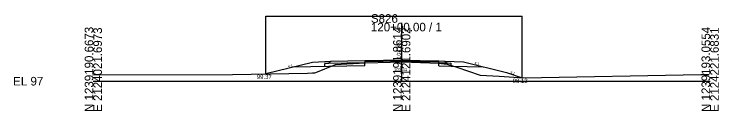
# Model space of a CAD drawing. Extents: x 2119282 to 2119710, y 1215030 to 1220057.
# Drawn here: x 2119381.9 to 2119610.4, y 1218530.1 to 1218561.7 of the extents above; entities that cross this region are included whole.
import ezdxf

# ---------------------------------------------------------------- set-up
doc = ezdxf.new("R2010")
doc.units = 0
for name, color, linetype in [('XS_CELL', 7, 'Continuous'), ('XS_M_DITCH', 7, 'Continuous'), ('XS_P_FINISHED_GRADE', 7, 'Continuous'), ('XS_P_FINISHED_GRADE_ELEV_TX', 7, 'Continuous'), ('XS_P_SUBGRADE_GRANULAR', 7, 'Continuous'), ('XS_P_SUBGRADE_PAVEMENT', 7, 'Continuous'), ('XS_P_TX_DCH', 7, 'Continuous'), ('XS_P_TX_FS_BS', 7, 'Continuous'), ('XS_X_GROUND', 7, 'Continuous'), ('XS_X_GROUND_TX', 7, 'Continuous')]:
    doc.layers.add(name, color=color, linetype=linetype)

msp = doc.modelspace()

# ---------------------------------------------------------------- linework, layer by layer
at = {"layer": 'XS_CELL'}
for p, q in [((2119507.6, 1218539.8), (2119507.6, 1218558.81)), ((2119407.6, 1218539.8), (2119507.6, 1218539.8)), ((2119507.6, 1218539.8), (2119607.6, 1218539.8))]:
    msp.add_line(p, q, dxfattribs=at)
at = {"layer": 'XS_M_DITCH'}
for p, q in [((2119463.57, 1218542.17), (2119463.57, 1218560.92)), ((2119463.57, 1218560.92), (2119546.66, 1218560.92)), ((2119546.66, 1218540.93), (2119546.66, 1218560.92))]:
    msp.add_line(p, q, dxfattribs=at)
at = {"layer": 'XS_P_FINISHED_GRADE'}
for p, q in [((2119478.62, 1218545.93), (2119463.57, 1218542.17)), ((2119484.62, 1218546.17), (2119478.62, 1218545.93)), ((2119495.6, 1218546.39), (2119484.62, 1218546.17)), ((2119507.6, 1218546.63), (2119495.6, 1218546.39)), ((2119507.6, 1218546.63), (2119519.6, 1218546.39)), ((2119519.6, 1218546.39), (2119521.6, 1218546.35)), ((2119521.6, 1218546.35), (2119527.6, 1218546.11)), ((2119527.6, 1218546.11), (2119541.6, 1218542.61)), ((2119541.6, 1218542.61), (2119546.66, 1218540.93))]:
    msp.add_line(p, q, dxfattribs=at)
at = {"layer": 'XS_P_SUBGRADE_GRANULAR'}
for p, q in [((2119483.97, 1218545.58), (2119482.62, 1218545.52)), ((2119482.62, 1218544.55), (2119482.62, 1218545.52)), ((2119495.6, 1218544.81), (2119495.61, 1218545.81)), ((2119519.6, 1218544.81), (2119519.59, 1218545.81)), ((2119522.26, 1218545.76), (2119523.6, 1218545.7)), ((2119523.6, 1218544.73), (2119523.6, 1218545.7)), ((2119483.97, 1218544.58), (2119472.26, 1218544.34)), ((2119495.6, 1218544.81), (2119483.97, 1218544.58)), ((2119519.6, 1218544.81), (2119523.6, 1218544.73)), ((2119523.6, 1218544.73), (2119533.97, 1218544.52))]:
    msp.add_line(p, q, dxfattribs=at)
at = {"layer": 'XS_P_SUBGRADE_PAVEMENT'}
for p, q in [((2119484.12, 1218545.83), (2119483.97, 1218545.58)), ((2119495.61, 1218545.81), (2119483.97, 1218545.58)), ((2119484.62, 1218546.17), (2119484.12, 1218545.83)), ((2119507.6, 1218546.3), (2119495.61, 1218546.06)), ((2119495.61, 1218545.81), (2119495.61, 1218546.06)), ((2119507.6, 1218546.3), (2119519.6, 1218546.06)), ((2119519.59, 1218545.81), (2119519.6, 1218546.06)), ((2119519.59, 1218545.81), (2119522.26, 1218545.76)), ((2119521.6, 1218546.35), (2119522.11, 1218546.01)), ((2119522.11, 1218546.01), (2119522.26, 1218545.76))]:
    msp.add_line(p, q, dxfattribs=at)
at = {"layer": 'XS_X_GROUND'}
for p, q in [((2119479.8, 1218542.67), (2119486.11, 1218545.27)), ((2119486.11, 1218545.27), (2119489.79, 1218545.44)), ((2119489.79, 1218545.44), (2119495.81, 1218545.73)), ((2119495.81, 1218545.73), (2119503.91, 1218546.01)), ((2119503.91, 1218546.01), (2119507.6, 1218546.13)), ((2119507.6, 1218546.13), (2119510.75, 1218545.98)), ((2119510.75, 1218545.98), (2119519.6, 1218545.65)), ((2119519.6, 1218545.65), (2119521.37, 1218545.5)), ((2119521.37, 1218545.5), (2119522.31, 1218545.37)), ((2119522.31, 1218545.37), (2119525.52, 1218544.34)), ((2119525.52, 1218544.34), (2119533.05, 1218541.78)), ((2119407.33, 1218541.85), (2119452.73, 1218541.94)), ((2119452.73, 1218541.94), (2119477.04, 1218542.46)), ((2119477.04, 1218542.46), (2119478.68, 1218542.55)), ((2119478.68, 1218542.55), (2119479.41, 1218542.53)), ((2119479.41, 1218542.53), (2119479.8, 1218542.67)), ((2119533.05, 1218541.78), (2119539.15, 1218541.44)), ((2119539.15, 1218541.44), (2119547.24, 1218540.89)), ((2119547.24, 1218540.89), (2119604.59, 1218541.95)), ((2119604.59, 1218541.95), (2119607.33, 1218542.01))]:
    msp.add_line(p, q, dxfattribs=at)

# ---------------------------------------------------------------- texts
at = {"layer": 'XS_CELL'}
for s, p in [('S826', (2119497.6, 1218558.81)), ('120+00.00 / 1', (2119497.6, 1218556.01)), ('EL 97', (2119381.6, 1218538.4))]:
    msp.add_text(s, height=2.8, dxfattribs=at).set_placement(p)
for s, p in [('N 1239190.6673', (2119407.6, 1218529.8)), ('E 2124021.6973', (2119410.4, 1218529.8)), ('N 1239191.8614', (2119507.6, 1218529.8)), ('E 2124121.6902', (2119510.4, 1218529.8)), ('N 1239193.0554', (2119607.6, 1218529.8)), ('E 2124221.6831', (2119610.4, 1218529.8))]:
    msp.add_text(s, height=2.8, rotation=90, dxfattribs=at).set_placement(p)
at = {"layer": 'XS_P_FINISHED_GRADE_ELEV_TX'}
msp.add_text('103.83', height=1.25, rotation=90, dxfattribs=at).set_placement((2119507.26, 1218547.13))
at = {"layer": 'XS_P_TX_DCH'}
for s, p in [('99.37', (2119460.62, 1218540.51)), ('98.13', (2119543.58, 1218539.22))]:
    msp.add_text(s, height=1.4, dxfattribs=at).set_placement(p)
at = {"layer": 'XS_P_TX_FS_BS'}
for s, rotation, p in [('4:1', 14.0362, (2119470.81, 1218544.2)), ('4:1', 345.9638, (2119531.11, 1218545.41)), ('3:1', 341.5651, (2119542.71, 1218542.39))]:
    msp.add_text(s, height=0.8, rotation=rotation, dxfattribs=at).set_placement(p)
at = {"layer": 'XS_X_GROUND_TX'}
msp.add_text('103.33', height=1, dxfattribs=at).set_placement((2119505.11, 1218543.08))

doc.saveas('drawing.dxf')
